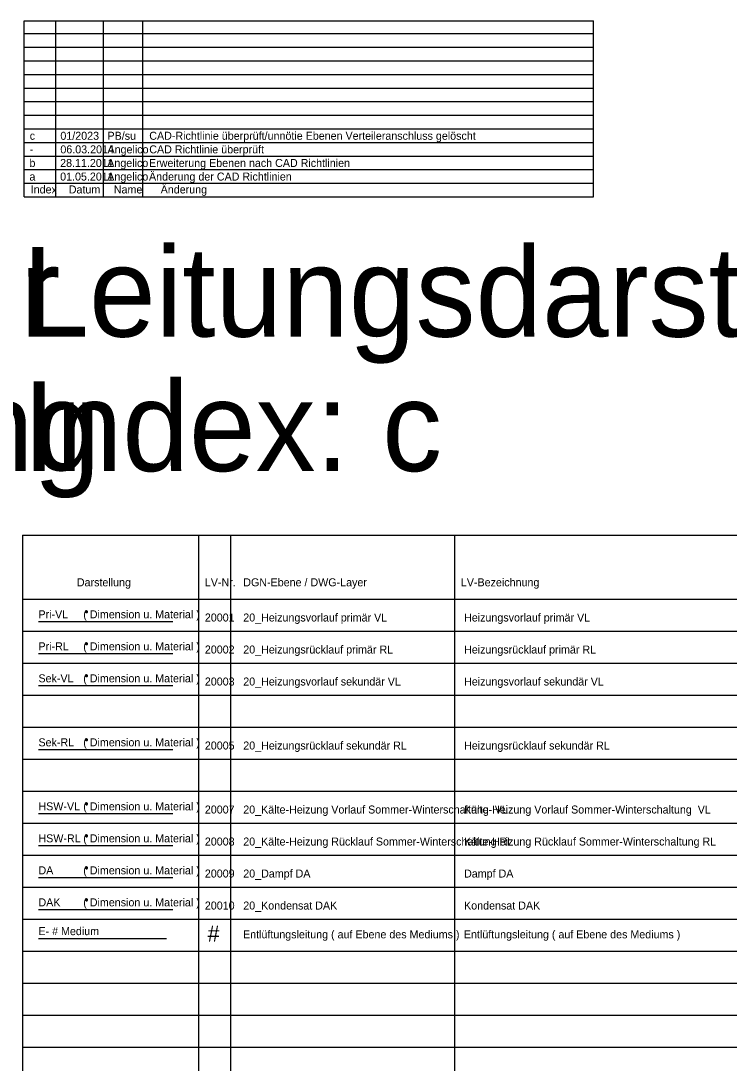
# Model space of a CAD drawing. Extents: x -29 to 48, y -113 to 16.
# Drawn here: x -0.05 to 22.08, y -16.5 to 16.07 of the extents above; entities that cross this region are included whole.
import ezdxf

# ---------------------------------------------------------------- set-up
doc = ezdxf.new("R2010")
doc.units = 0
for name, color, linetype in [('20_Dampf DA', 7, 'Continuous'), ('20_Heizungsrücklauf primär RL', 7, 'Continuous'), ('20_Heizungsrücklauf sekundär RL', 7, 'Continuous'), ('20_Heizungsvorlauf primär VL', 7, 'Continuous'), ('20_Heizungsvorlauf sekundär VL', 7, 'Continuous'), ('20_Kondensat DAK', 7, 'Continuous'), ('20_Kälte-Heizung Rücklauf Sommer-Winterschaltung RL', 7, 'Continuous'), ('20_Kälte-Heizung Vorlauf Sommer-Winterschaltung  VL', 7, 'Continuous'), ('20_z_freie_Ebene_01', 7, 'Continuous'), ('Default', 7, 'Continuous')]:
    doc.layers.add(name, color=color, linetype=linetype)

msp = doc.modelspace()

# ---------------------------------------------------------------- linework, layer by layer
at = {"layer": '20_Dampf DA'}
for p, q in [((1.956, -10.4), (2.044, -10.4)), ((1.969, -10.369), (2.031, -10.431)), ((2.031, -10.369), (1.969, -10.431)), ((2, -10.356), (2, -10.444)), ((0.5, -10.7), (4.7, -10.7))]:
    msp.add_line(p, q, dxfattribs=at)
at = {"layer": '20_Heizungsrücklauf primär RL'}
for p, q in [((1.956, -3.4), (2.044, -3.4)), ((1.969, -3.369), (2.031, -3.431)), ((2.031, -3.369), (1.969, -3.431)), ((2, -3.356), (2, -3.444)), ((0.5, -3.7), (4.7, -3.7))]:
    msp.add_line(p, q, dxfattribs=at)
at = {"layer": '20_Heizungsrücklauf sekundär RL'}
for p, q in [((1.956, -6.4), (2.044, -6.4)), ((1.969, -6.369), (2.031, -6.431)), ((2.031, -6.369), (1.969, -6.431)), ((2, -6.356), (2, -6.444)), ((0.5, -6.7), (4.7, -6.7))]:
    msp.add_line(p, q, dxfattribs=at)
at = {"layer": '20_Heizungsvorlauf primär VL'}
for p, q in [((1.956, -2.4), (2.044, -2.4)), ((1.969, -2.369), (2.031, -2.431)), ((2.031, -2.369), (1.969, -2.431)), ((2, -2.356), (2, -2.444)), ((0.5, -2.7), (4.7, -2.7))]:
    msp.add_line(p, q, dxfattribs=at)
at = {"layer": '20_Heizungsvorlauf sekundär VL'}
for p, q in [((1.956, -4.4), (2.044, -4.4)), ((1.969, -4.369), (2.031, -4.431)), ((2.031, -4.369), (1.969, -4.431)), ((2, -4.356), (2, -4.444)), ((0.5, -4.7), (4.7, -4.7))]:
    msp.add_line(p, q, dxfattribs=at)
at = {"layer": '20_Kondensat DAK'}
for p, q in [((1.969, -11.369), (2.031, -11.431)), ((2.031, -11.369), (1.969, -11.431)), ((2, -11.356), (2, -11.444)), ((0.5, -11.7), (4.7, -11.7)), ((1.956, -11.4), (2.044, -11.4))]:
    msp.add_line(p, q, dxfattribs=at)
at = {"layer": '20_Kälte-Heizung Rücklauf Sommer-Winterschaltung RL'}
for p, q in [((1.956, -9.4), (2.044, -9.4)), ((1.969, -9.369), (2.031, -9.431)), ((2.031, -9.369), (1.969, -9.431)), ((2, -9.356), (2, -9.444)), ((0.5, -9.7), (4.7, -9.7))]:
    msp.add_line(p, q, dxfattribs=at)
at = {"layer": '20_Kälte-Heizung Vorlauf Sommer-Winterschaltung  VL'}
for p, q in [((1.956, -8.4), (2.044, -8.4)), ((1.969, -8.369), (2.031, -8.431)), ((2.031, -8.369), (1.969, -8.431)), ((2, -8.356), (2, -8.444)), ((0.5, -8.7), (4.7, -8.7))]:
    msp.add_line(p, q, dxfattribs=at)
at = {"layer": '20_z_freie_Ebene_01'}
msp.add_line((0.5, -12.6), (4.5, -12.6), dxfattribs=at)
at = {"layer": 'Default'}
for p, q in [((0.058, 10.57), (0.058, 16.069)), ((0.058, 16.069), (17.846, 16.069)), ((1.046, 10.57), (1.046, 16.069)), ((2.529, 10.57), (2.529, 16.069)), ((3.764, 10.57), (3.764, 16.069)), ((17.846, 10.57), (17.846, 16.069)), ((0.058, 15.67), (17.846, 15.67)), ((0.058, 15.245), (17.846, 15.245)), ((0.058, 14.82), (17.846, 14.82)), ((0.058, 14.395), (17.846, 14.395)), ((0.058, 13.97), (17.846, 13.97)), ((0.058, 13.545), (17.846, 13.545)), ((0.058, 13.12), (17.846, 13.12)), ((0.058, 12.695), (17.846, 12.695)), ((0.058, 12.27), (17.846, 12.27)), ((0.058, 11.845), (17.846, 11.845)), ((0.058, 11.42), (17.846, 11.42)), ((0.058, 10.995), (17.846, 10.995)), ((0.058, 10.57), (17.846, 10.57)), ((0.058, 10.57), (17.846, 10.57)), ((0, 0), (0, -107)), ((0, 0), (32, 0)), ((5.5, 0), (5.5, -107)), ((6.5, 0), (6.5, -107)), ((13.5, 0), (13.5, -107)), ((0, -2), (28.338, -2)), ((0, -2), (32, -2)), ((0, -3), (32, -3)), ((0, -4), (32, -4)), ((0, -5), (32, -5)), ((0, -6), (32, -6)), ((0, -7), (32, -7)), ((0, -8), (32, -8)), ((0, -9), (32, -9)), ((0, -10), (32, -10)), ((0, -11), (32, -11)), ((0, -12), (32, -12)), ((0, -13), (32, -13)), ((0, -14), (32, -14)), ((0, -15), (32, -15)), ((0, -16), (32, -16))]:
    msp.add_line(p, q, dxfattribs=at)

# ---------------------------------------------------------------- texts
at = {"layer": '20_Dampf DA'}
for s, p in [('DA', (0.5, -10.6)), ('( Dimension u. Material )', (1.9, -10.6))]:
    msp.add_text(s, height=0.25, dxfattribs=at).set_placement(p)
at = {"layer": '20_Heizungsrücklauf primär RL'}
for s, p in [('Pri-RL', (0.5, -3.6)), ('( Dimension u. Material )', (1.9, -3.6))]:
    msp.add_text(s, height=0.25, dxfattribs=at).set_placement(p)
at = {"layer": '20_Heizungsrücklauf sekundär RL'}
for s, p in [('Sek-RL', (0.5, -6.6)), ('( Dimension u. Material )', (1.9, -6.6))]:
    msp.add_text(s, height=0.25, dxfattribs=at).set_placement(p)
at = {"layer": '20_Heizungsvorlauf primär VL'}
for s, p in [('Pri-VL', (0.5, -2.6)), ('( Dimension u. Material )', (1.9, -2.6))]:
    msp.add_text(s, height=0.25, dxfattribs=at).set_placement(p)
at = {"layer": '20_Heizungsvorlauf sekundär VL'}
for s, p in [('Sek-VL', (0.5, -4.6)), ('( Dimension u. Material )', (1.9, -4.6))]:
    msp.add_text(s, height=0.25, dxfattribs=at).set_placement(p)
at = {"layer": '20_Kondensat DAK'}
for s, p in [('DAK', (0.5, -11.6)), ('( Dimension u. Material )', (1.9, -11.6))]:
    msp.add_text(s, height=0.25, dxfattribs=at).set_placement(p)
at = {"layer": '20_Kälte-Heizung Rücklauf Sommer-Winterschaltung RL'}
for s, p in [('HSW-RL', (0.5, -9.6)), ('( Dimension u. Material )', (1.9, -9.6))]:
    msp.add_text(s, height=0.25, dxfattribs=at).set_placement(p)
at = {"layer": '20_Kälte-Heizung Vorlauf Sommer-Winterschaltung  VL'}
for s, p in [('HSW-VL', (0.5, -8.6)), ('( Dimension u. Material )', (1.9, -8.6))]:
    msp.add_text(s, height=0.25, dxfattribs=at).set_placement(p)
at = {"layer": '20_z_freie_Ebene_01'}
msp.add_text('E- # Medium', height=0.25, dxfattribs=at).set_placement((0.5, -12.5))
at = {"layer": 'Default'}
for s, height, p in [('c     ', 0.25, (0.227, 12.353)), ('01/2023   ', 0.25, (1.185, 12.353)), ('PB/su   ', 0.25, (2.658, 12.353)), ('CAD-Richtlinie überprüft/unnötie Ebenen Verteileranschluss gelöscht                             ', 0.25, (3.963, 12.353)), ('06.03.2014', 0.25, (1.185, 11.928)), ('Angelico', 0.25, (2.658, 11.928)), ('CAD Richtlinie überprüft                                                                        ', 0.25, (3.963, 11.928)), ('b     ', 0.25, (0.219, 11.503)), ('-     ', 0.25, (0.227, 11.928)), ('28.11.2011', 0.25, (1.178, 11.503)), ('Angelico', 0.25, (2.65, 11.503)), ('Erweiterung Ebenen nach CAD Richtlinien                                                         ', 0.25, (3.955, 11.503)), ('a     ', 0.25, (0.219, 11.078)), ('01.05.2011', 0.25, (1.178, 11.078)), ('Angelico', 0.25, (2.65, 11.078)), ('Änderung der CAD Richtlinien                                                                    ', 0.25, (3.955, 11.078)), ('Index', 0.25, (0.259, 10.675)), ('Datum', 0.25, (1.448, 10.675)), ('Name', 0.25, (2.855, 10.675)), ('Änderung', 0.25, (4.319, 10.675)), ('Musterlegende für ', 2.8, (-29, 6.2)), ('Leitungsdarstellung: Heizung ', 2.8, (0, 6.2)), ('Blattpläne Heizung', 2.8, (-29, 2)), ('Index: c', 2.8, (0, 2)), ('Darstellung', 0.25, (1.7, -1.6)), ('LV-Nr.', 0.25, (5.7, -1.6)), ('DGN-Ebene / DWG-Layer', 0.25, (6.9, -1.6)), ('LV-Bezeichnung', 0.25, (13.7, -1.6)), ('20001', 0.25, (5.7, -2.7)), ('20_Heizungsvorlauf primär VL', 0.25, (6.9, -2.7)), ('Heizungsvorlauf primär VL', 0.25, (13.8, -2.7)), ('20002', 0.25, (5.7, -3.7)), ('20_Heizungsrücklauf primär RL', 0.25, (6.9, -3.7)), ('Heizungsrücklauf primär RL', 0.25, (13.8, -3.7)), ('20003', 0.25, (5.7, -4.7)), ('20_Heizungsvorlauf sekundär VL', 0.25, (6.9, -4.7)), ('Heizungsvorlauf sekundär VL', 0.25, (13.8, -4.7)), ('20005', 0.25, (5.7, -6.7)), ('20_Heizungsrücklauf sekundär RL', 0.25, (6.9, -6.7)), ('Heizungsrücklauf sekundär RL', 0.25, (13.8, -6.7)), ('20007', 0.25, (5.7, -8.7)), ('20_Kälte-Heizung Vorlauf Sommer-Winterschaltung  VL', 0.25, (6.9, -8.7)), ('Kälte-Heizung Vorlauf Sommer-Winterschaltung  VL', 0.25, (13.8, -8.7)), ('20_Kälte-Heizung Rücklauf Sommer-Winterschaltung RL', 0.25, (6.9, -9.7)), ('Kälte-Heizung Rücklauf Sommer-Winterschaltung RL', 0.25, (13.8, -9.7)), ('20008', 0.25, (5.7, -9.7)), ('20009', 0.25, (5.7, -10.7)), ('20_Dampf DA', 0.25, (6.9, -10.7)), ('Dampf DA', 0.25, (13.8, -10.7)), ('20010', 0.25, (5.7, -11.7)), ('20_Kondensat DAK', 0.25, (6.9, -11.7)), ('Kondensat DAK', 0.25, (13.8, -11.7)), (' # ', 0.5, (5.6, -12.7)), (' Entlüftungsleitung ( auf Ebene des Mediums )', 0.25, (6.8, -12.6)), (' Entlüftungsleitung ( auf Ebene des Mediums )', 0.25, (13.7, -12.6))]:
    msp.add_text(s, height=height, dxfattribs=at).set_placement(p)

doc.saveas('drawing.dxf')
